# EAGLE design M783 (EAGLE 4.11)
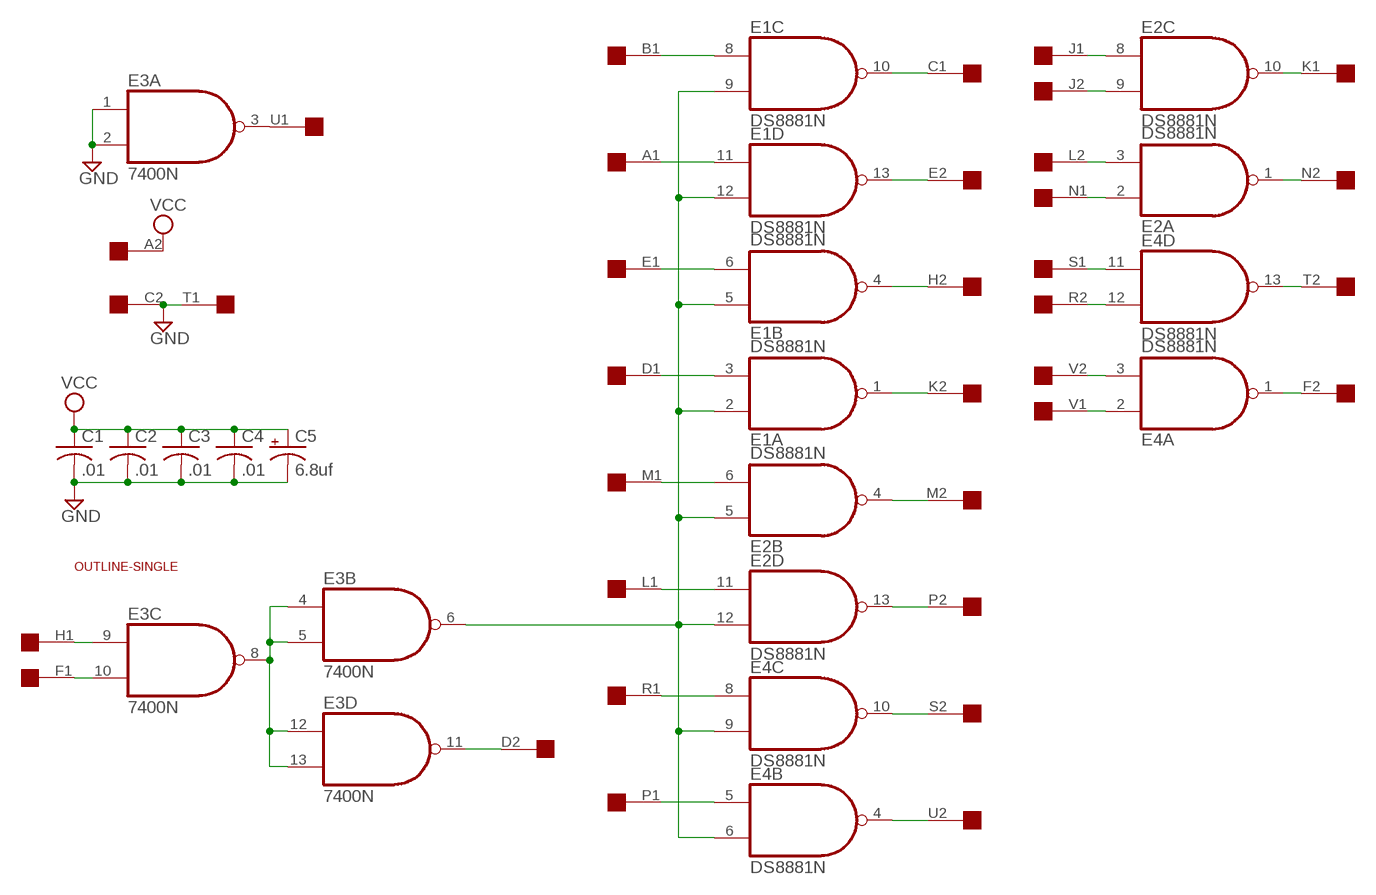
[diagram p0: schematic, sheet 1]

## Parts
C1  .01  C-US050-025X075  [C050-025X075]
C2  .01  C-US050-025X075  [C050-025X075]
C3  .01  C-US050-025X075  [C050-025X075]
C4  .01  C-US050-025X075  [C050-025X075]
C5  6.8uf  CPOL-USE15-5AXIAL  [E15-5]
E1  DS8881N  [DIL14]
E2  DS8881N  [DIL14]
E3  7400N  [DIL14]
E4  DS8881N  [DIL14]
U$1  SINGLE  [EDGE-CON2]
U$2  OUTLINE-SINGLE  [SINGLE]

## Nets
GND: C1.2 C2.2 C3.2 C4.2 C5.- E3.1(A:I0) E3.2(A:I1) U$1.C2 U$1.T1
N$1: E3.3(A:O) U$1.U1
N$2: E1.2(A:I0) E1.5(B:I0) E1.9(C:I1) E1.12(D:I1) E2.5(B:I0) E2.12(D:I1) E3.6(B:O) E4.6(B:I1) E4.9(C:I1)
N$3: E2.4(B:O) U$1.M2
N$4: E2.13(D:O) U$1.P2
N$5: E4.5(B:I0) U$1.P1
N$6: E4.8(C:I0) U$1.R1
N$7: E4.10(C:O) U$1.S2
N$8: E2.11(D:I0) U$1.L1
N$9: E4.4(B:O) U$1.U2
N$10: E2.6(B:I1) U$1.M1
N$11: E1.10(C:O) U$1.C1
N$12: E1.8(C:I0) U$1.B1
N$13: E1.13(D:O) U$1.E2
N$14: E1.11(D:I0) U$1.A1
N$15: E1.4(B:O) U$1.H2
N$16: E1.6(B:I1) U$1.E1
N$17: E1.1(A:O) U$1.K2
N$18: E1.3(A:I1) U$1.D1
N$19: E3.11(D:O) U$1.D2
N$20: E4.1(A:O) U$1.F2
N$21: E4.13(D:O) U$1.T2
N$22: E2.1(A:O) U$1.N2
N$23: E2.10(C:O) U$1.K1
N$24: E2.8(C:I0) U$1.J1
N$25: E2.9(C:I1) U$1.J2
N$26: E2.3(A:I1) U$1.L2
N$27: E2.2(A:I0) U$1.N1
N$28: E4.11(D:I0) U$1.S1
N$29: E4.12(D:I1) U$1.R2
N$30: E3.4(B:I0) E3.5(B:I1) E3.8(C:O) E3.12(D:I0) E3.13(D:I1)
N$31: E3.9(C:I0) U$1.H1
N$32: E3.10(C:I1) U$1.F1
N$33: E4.3(A:I1) U$1.V2
N$34: E4.2(A:I0) U$1.V1
VCC: C1.1 C2.1 C3.1 C4.1 C5.+ U$1.A2
Unconnected: U$1.B2

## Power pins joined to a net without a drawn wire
GND: E1.7(P:GND) E2.7(P:GND) E3.7(P:GND) E4.7(P:GND)
VCC: E1.14(P:VCC) E2.14(P:VCC) E3.14(P:VCC) E4.14(P:VCC)

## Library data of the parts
C1-C4 = rcl:C-US: CAPACITOR, American symbol
C5 = rcl:CPOL-US: POLARIZED CAPACITOR, American symbol
E1 E2 E4 = dec-con:DS8881: Quad 2-input NAND gate, open collector
E3 = 74xx-jameco:74*00: Quad 2-input NAND gate
U$1 = dec-con:SINGLE: Single-Height DEC board
U$2 = dec-con:OUTLINE-*: Board outlines for DEC boards.

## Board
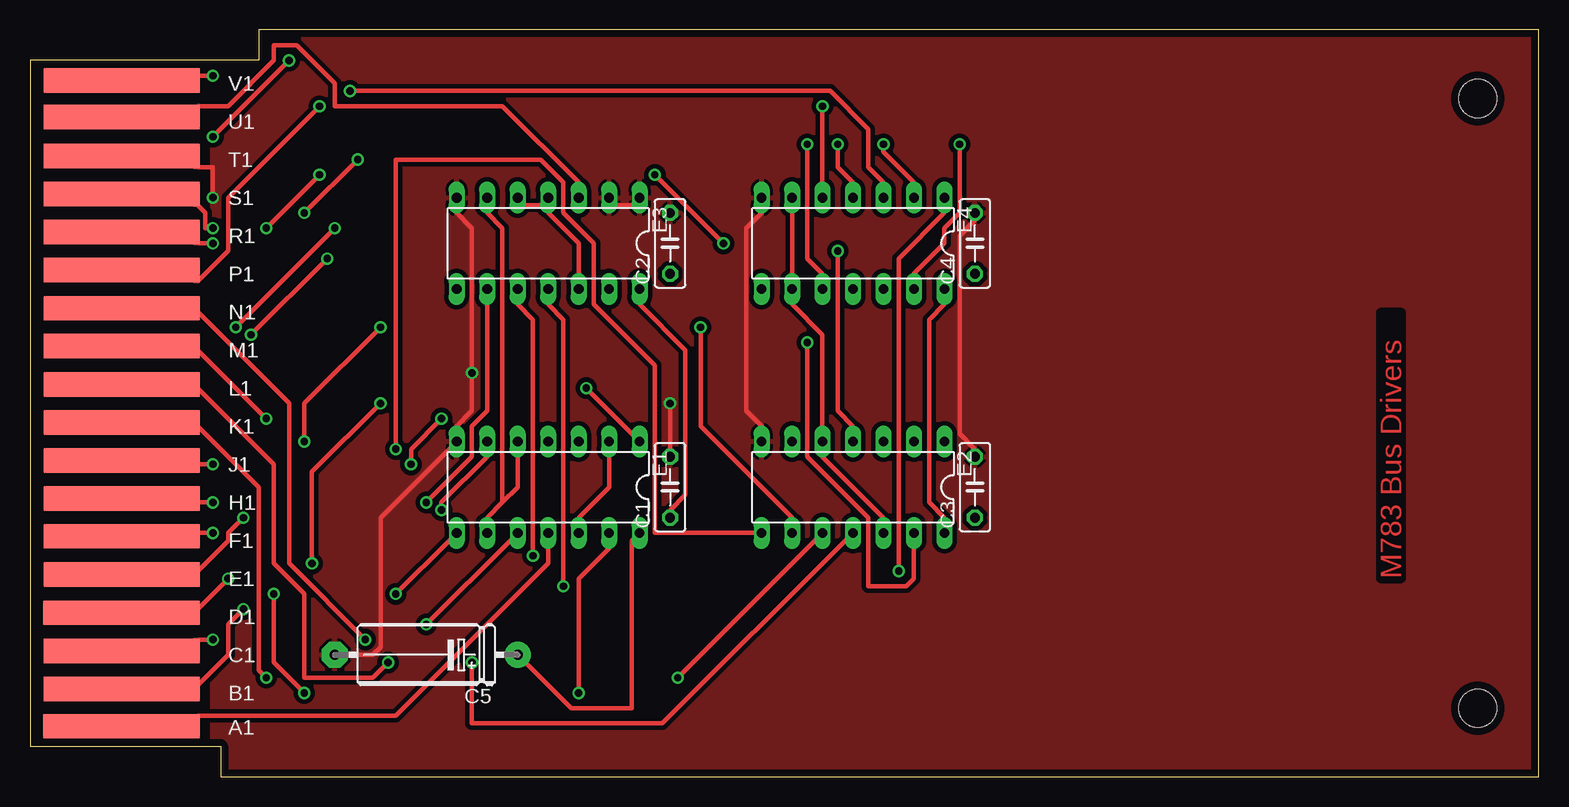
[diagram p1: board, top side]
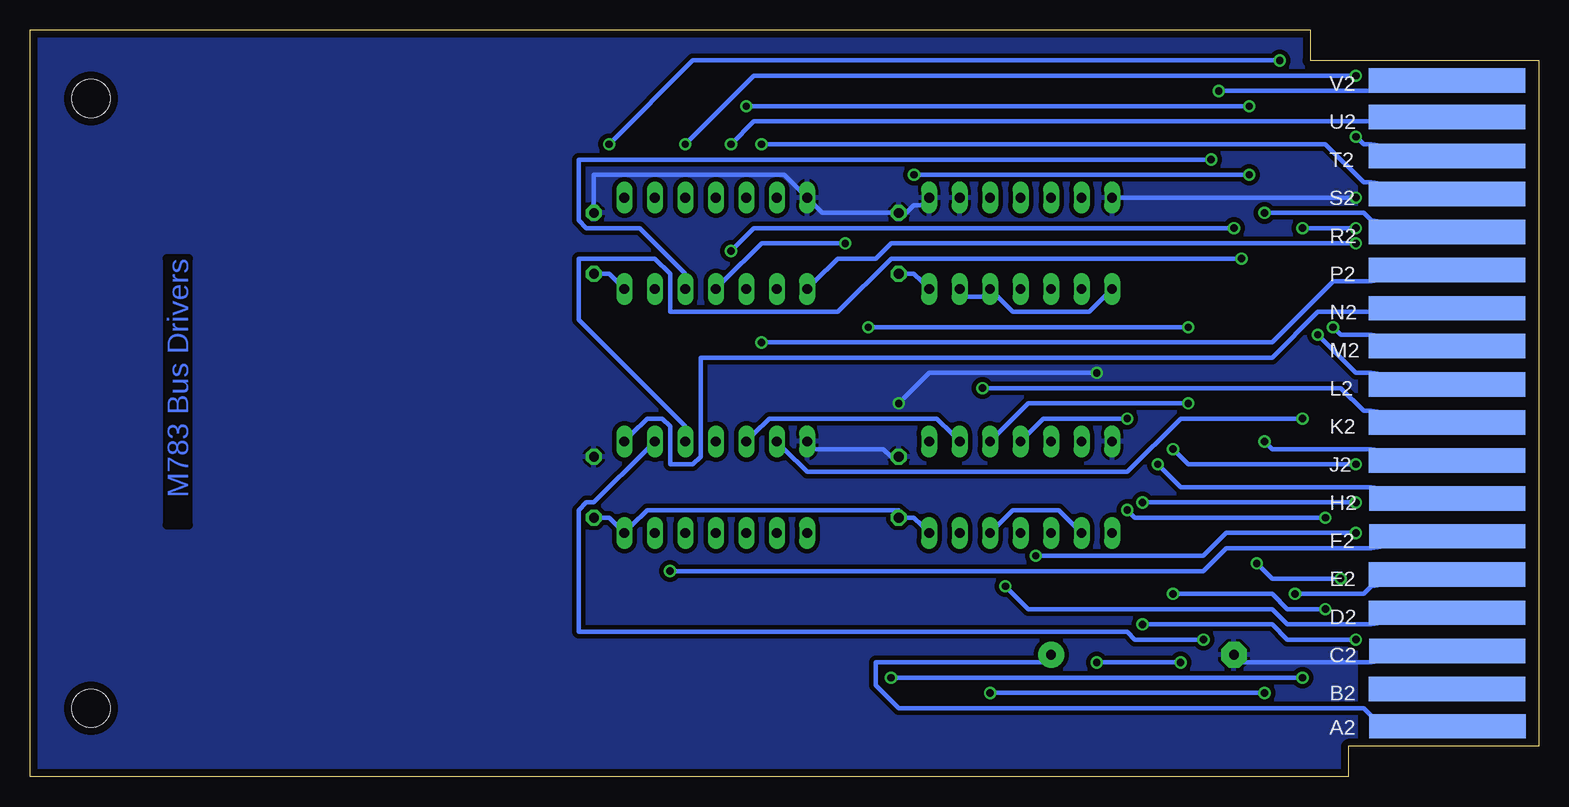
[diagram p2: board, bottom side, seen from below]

Size 125.73 x 62.23 mm. Coordinates in mm from the lower left corner, seen from the top.
Copper layers (1*16): Top 0.035mm / dielectric 1.5mm / Bottom 0.035mm
Design rules "15mils": minimum track width 15mil, minimum drill 24mil, track to track 15mil, track to pad 10mil, pad to pad 10mil, via to via 10mil, smd to smd 10mil, copper to edge 25mil, drill to drill 10mil, minimum pad ring 10mil, minimum via ring 8mil, stop-mask expansion 0mil, vias tented up to drill 0mil, thermal gap 10mil

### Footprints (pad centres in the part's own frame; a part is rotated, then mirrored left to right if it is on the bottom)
C050-025X075 = drill 0.813 octagon: 1 -2.54,0; 2 2.54,0
E15-5 = drill 0.813 pad 2.159 round: + -7.62,0 | drill 0.813 pad 2.159 octagon: - 7.62,0
DIL14 = drill 0.813 long: 1 -7.62,-3.81; 2 -5.08,-3.81; 3 -2.54,-3.81; 4 0,-3.81; 5 2.54,-3.81; 6 5.08,-3.81; 7 7.62,-3.81; 8 7.62,3.81; 9 5.08,3.81; 10 2.54,3.81; 11 0,3.81; 12 -2.54,3.81; 13 -5.08,3.81; 14 -7.62,3.81
EDGE-CON2 = smd 13.017 x 2.032: A1 7.633,4.207; B1 7.639,7.327; C1 7.636,10.489; D1 7.633,13.665; E1 7.642,16.84; F1 7.642,20.041; H1 7.642,23.19; J1 7.642,26.34; K1 7.642,29.515; L1 7.642,32.69; M1 7.642,35.89; N1 7.642,39.04; P1 7.642,42.24; R1 7.642,45.39; S1 7.642,48.565; T1 7.642,51.74; U1 7.642,54.966; V1 7.642,58.026 | smd 13.017 x 2.032 bottom: A2 7.614,4.207; B2 7.642,7.328; C2 7.617,10.49; D2 7.642,13.665; E2 7.642,16.84; F2 7.617,20.041; H2 7.617,23.19; J2 7.642,26.34; K2 7.642,29.515; L2 7.642,32.69; M2 7.642,35.89; N2 7.642,39.04; P2 7.642,42.24; R2 7.642,45.39; S2 7.642,48.565; T2 7.642,51.74; U2 7.642,54.966; V2 7.642,58.026
SINGLE = hole 3.175: 120.65,56.515; 120.65,5.715

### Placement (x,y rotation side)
C1  53.34,24.13 90 top
C2  53.34,44.45 90 top
C3  78.74,24.13 90 top
C4  78.74,44.45 90 top
C5  33.02,10.16 180 top
E1  43.18,24.13 180 top
E2  68.58,24.13 180 top
E3  43.18,44.45 180 top
E4  68.58,44.45 180 top
U$1  0,0 0 top
U$2  0,0 0 top

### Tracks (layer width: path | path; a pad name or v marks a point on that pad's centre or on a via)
GND  (via drill 0.61)
  Top 0.381: C3.2 78.74,27.3 77.47,28.57 77.47,45.09 78.74,46.35 C4.2 | E3.2 48.9,47.62 50.17,47.62 E3.1 | E2.7 60.96,29.21 59.69,30.48 59.69,45.72 60.96,46.99 E4.7 | E3.7 35.56,46.99 36.83,45.72 v36.83,33.66 36.83,30.48 35.56,29.21 E1.7 34.93,27.3 29.21,21.59 29.21,10.79 28.58,10.16 26.04,10.16 C5.- | v15.24,48.26 15.24,50.8 13.97,50.8 U$1.T1 | v53.34,31.11 53.34,27.3 C1.2
  Bottom 0.381: C1.2 53.98,26.67 54.61,27.3 60.33,27.3 E2.7 | E3.1 51.44,47.62 52.07,47.62 52.71,46.99 C2.2 53.98,46.99 59.69,46.99 60.33,47.62 E4.7 61.6,48.9 62.87,50.16 78.74,50.16 78.74,47.62 C4.2 | C5.- 24.77,9.53 13.97,9.53 U$1.C2 | v15.24,48.26 34.93,48.26 E3.7 | v53.34,31.11 50.8,33.66 v36.83,33.66
  pour Top (isolate 0.305): 15.24,62.23 125.73,62.23 125.73,0 15.24,0
  pour Bottom (isolate 0.305): 15.24,62.23 125.73,62.23 125.73,0 15.24,0
N$1
  Top 0.381: E3.3 45.72,49.53 39.37,55.88 25.4,55.88 25.4,57.78 22.23,60.96 20.32,60.96 20.32,59.69 16.51,55.88 13.97,55.88 U$1.U1
N$2
  Top 0.381: E4.6 63.5,46.99 63.5,41.91 E4.9 63.5,39.37 66.04,36.83 66.04,29.21 E2.5 66.04,26.67 71.12,21.59 E2.12 | E1.12 45.72,21.59 48.26,24.13 48.26,26.67 E1.2 | 39.37,22.86 40.64,24.13 40.64,26.67 E1.5 | 39.37,22.86 38.1,21.59 E1.9 | 39.37,22.86 39.37,45.72 38.1,46.99 E3.6
  Bottom 0.381: E1.12 45.09,20.95 43.82,22.23 40.01,22.23 38.74,20.95 E1.9 | E2.5 65.41,28.57 64.14,29.84 50.17,29.84 48.9,28.57 E1.2
N$3  (via drill 0.61)
  Top 0.381: v67.31,43.81 67.31,30.48 68.58,29.21 E2.4 | v17.15,37.47 v25.4,45.72
  Bottom 0.381: v67.31,43.81 65.41,45.72 v25.4,45.72 | v17.15,37.47 16.51,36.83 13.97,36.83 U$1.M2
N$4  (via drill 0.61)
  Top 0.381: v64.77,36.2 64.77,26.67 69.85,21.59 69.85,15.88 73.03,15.88 73.66,16.51 73.66,19.05 E2.13
  Bottom 0.381: v64.77,36.2 22.23,36.2 17.15,41.27 13.97,41.27 U$1.P2
N$5  (via drill 0.61)
  Top 0.381: v66.04,55.88 66.04,49.53 E4.5 | v24.13,55.88 16.51,48.26 16.51,43.81 13.97,41.27 U$1.P1
  Bottom 0.381: v24.13,55.88 v66.04,55.88
N$6  (via drill 0.61)
  Top 0.381: v15.24,44.45 13.97,44.45 U$1.R1
  Bottom 0.381: v15.24,44.45 53.98,44.45 55.25,43.18 58.42,43.18 60.33,41.27 E4.8
N$7  (via drill 0.61)
  Top 0.381: v64.77,52.7 64.77,43.18 66.04,41.91 E4.10
  Bottom 0.381: v64.77,52.7 17.78,52.7 14.61,49.53 13.97,49.53 U$1.S2
N$8  (via drill 0.61)
  Top 0.381: v36.83,9.53 36.83,4.45 52.71,4.45 67.95,19.68 E2.11 | v29.85,9.53 28.58,8.26 22.86,8.26 22.86,15.24 20.32,17.78 20.32,26.04 13.97,32.38 U$1.L1
  Bottom 0.381: v29.85,9.53 v36.83,9.53
N$9  (via drill 0.61)
  Top 0.381: v67.31,52.7 67.31,50.8 68.58,49.53 E4.4
  Bottom 0.381: v67.31,52.7 65.41,54.61 13.97,54.61 U$1.U2
N$10  (via drill 0.61)
  Top 0.381: v19.69,29.84 13.97,35.56 U$1.M1
  Bottom 0.381: v19.69,29.84 29.85,29.84 34.29,25.4 60.96,25.4 62.87,27.3 E2.6
N$11  (via drill 0.61)
  Top 0.381: v33.02,12.7 40.01,19.68 E1.10 | v15.24,11.43 13.97,11.43 U$1.C1
  Bottom 0.381: v33.02,12.7 22.23,12.7 20.96,11.43 v15.24,11.43
N$12  (via drill 0.61)
  Top 0.381: v30.48,15.24 34.93,19.68 E1.8 | v17.78,13.97 16.51,12.7 16.51,10.16 13.97,7.62 U$1.B1
  Bottom 0.381: v30.48,15.24 22.23,15.24 20.96,13.97 v17.78,13.97
N$13  (via drill 0.61)
  Top 0.381: v45.72,6.99 45.72,16.51 48.26,19.05 E1.13 | v22.86,6.99 20.32,9.53 v20.32,15.24
  Bottom 0.381: v22.86,6.99 v45.72,6.99 | v20.32,15.24 14.61,15.24 13.97,15.88 U$1.E2
N$14
  Top 0.381: E1.11 43.18,19.05 43.18,17.78 30.48,5.08 13.97,5.08 U$1.A1
N$15  (via drill 0.61)
  Top 0.381: v34.29,29.84 31.75,27.3 v31.75,26.04
  Bottom 0.381: v34.29,29.84 41.28,29.84 42.55,28.57 E1.4 | v31.75,26.04 29.85,24.13 13.97,24.13 U$1.H2
N$16  (via drill 0.61)
  Top 0.381: v34.29,22.23 34.29,22.86 38.1,26.67 E1.6 | v17.78,21.59 16.51,20.32 16.51,19.68 13.97,17.14 U$1.E1
  Bottom 0.381: v34.29,22.23 33.66,21.59 v17.78,21.59
N$17  (via drill 0.61)
  Top 0.381: v46.36,32.38 50.17,28.57 E1.1
  Bottom 0.381: v46.36,32.38 16.51,32.38 14.61,30.48 13.97,30.48 U$1.K2
N$18  (via drill 0.61)
  Top 0.381: v29.21,31.11 23.5,25.4 v23.5,17.78 | v16.51,16.51 13.97,13.97 U$1.D1
  Bottom 0.381: v29.21,31.11 42.55,31.11 45.09,28.57 E1.3 | v23.5,17.78 22.23,16.51 v16.51,16.51
N$19  (via drill 0.61)
  Top 0.381: v44.45,15.88 44.45,38.1 43.18,39.37 E3.11
  Bottom 0.381: v44.45,15.88 42.55,13.97 22.23,13.97 20.96,12.7 13.97,12.7 U$1.D2
N$20  (via drill 0.61)
  Top 0.381: v72.39,17.14 72.39,43.18 76.2,46.99 E4.1
  Bottom 0.381: v72.39,17.14 27.94,17.14 26.04,19.05 13.97,19.05 U$1.F2
N$21  (via drill 0.61)
  Top 0.381: v77.47,52.7 77.47,46.99 76.2,45.72 76.2,44.45 73.66,41.91 E4.13 | v15.24,53.34 v21.59,59.69
  Bottom 0.381: v77.47,52.7 70.49,59.69 v21.59,59.69 | v15.24,53.34 14.61,52.7 13.97,52.7 U$1.T2
N$22
  Bottom 0.381: E2.1 75.57,28.57 74.3,29.84 73.03,29.84 72.39,29.21 72.39,26.04 70.49,26.04 69.85,26.67 69.85,34.92 22.23,34.92 18.42,38.73 13.97,38.73 U$1.N2
N$23  (via drill 0.61)
  Top 0.381: v53.98,8.26 65.41,19.68 E2.10 | v19.69,8.26 19.05,8.89 19.05,24.13 13.97,29.21 U$1.K1
  Bottom 0.381: v19.69,8.26 v53.98,8.26
N$24  (via drill 0.61)
  Top 0.381: v30.48,27.3 30.48,51.44 42.55,51.44 44.45,49.53 44.45,46.99 46.99,44.45 46.99,39.37 52.07,34.29 52.07,20.32 60.33,20.32 E2.8 | v15.24,26.04 13.97,26.04 U$1.J1
  Bottom 0.381: v30.48,27.3 29.21,26.04 v15.24,26.04
N$25  (via drill 0.61)
  Top 0.381: v55.88,37.47 55.88,29.21 63.5,21.59 E2.9 | v29.21,37.47 22.86,31.11 v22.86,27.94
  Bottom 0.381: v29.21,37.47 v55.88,37.47 | v22.86,27.94 22.23,27.3 13.97,27.3 U$1.J2
N$26  (via drill 0.61)
  Top 0.381: v18.42,36.83 v24.77,43.18
  Bottom 0.381: v24.77,43.18 53.98,43.18 58.42,38.73 72.39,38.73 72.39,41.91 73.66,43.18 80.01,43.18 80.01,38.1 71.12,29.21 E2.3 | v18.42,36.83 15.24,33.66 13.97,33.66 U$1.L2
N$27  (via drill 0.61)
  Top 0.381: v27.94,11.43 21.59,17.78 21.59,31.11 13.97,38.73 U$1.N1
  Bottom 0.381: v27.94,11.43 33.66,11.43 34.29,12.06 80.01,12.06 80.01,22.23 79.38,22.86 78.74,22.86 74.3,27.3 E2.2
N$28  (via drill 0.61)
  Top 0.381: v52.07,50.16 v57.79,44.45 | v19.69,45.72 v24.13,50.16 | v15.24,45.72 14.61,45.72 14.61,46.99 13.97,47.62 U$1.S1
  Bottom 0.381: v57.79,44.45 64.77,44.45 67.95,41.27 E4.11 | v24.13,50.16 v52.07,50.16 | v15.24,45.72 v19.69,45.72
N$29  (via drill 0.61)
  Top 0.381: v22.86,46.99 v27.31,51.44
  Bottom 0.381: v27.31,51.44 80.01,51.44 80.01,46.35 79.38,45.72 74.93,45.72 71.12,41.91 E4.12 | v22.86,46.99 14.61,46.99 13.97,46.35 U$1.R2
N$30
  Top 0.381: E3.5 41.28,47.62 42.55,47.62 E3.4 43.18,46.99 45.72,44.45 45.72,41.91 E3.12
  Bottom 0.381: E3.8 36.2,40.01 37.47,38.73 43.82,38.73 45.09,40.01 E3.12 46.36,40.01 47.63,40.01 E3.13
N$31  (via drill 0.61)
  Top 0.381: v33.02,22.86 36.83,26.67 36.83,29.21 38.1,30.48 38.1,39.37 E3.9 | v15.24,22.86 13.97,22.86 U$1.H1
  Bottom 0.381: v15.24,22.86 v33.02,22.86
N$32  (via drill 0.61)
  Top 0.381: v41.91,18.41 41.91,38.1 40.64,39.37 E3.10 | v15.24,20.32 13.97,20.32 U$1.F1
  Bottom 0.381: v41.91,18.41 27.94,18.41 26.04,20.32 v15.24,20.32
N$33  (via drill 0.61)
  Top 0.381: v26.67,57.15 66.68,57.15 69.85,53.98 69.85,50.8 71.12,49.53 E4.3
  Bottom 0.381: v26.67,57.15 13.97,57.15 U$1.V2
N$34  (via drill 0.61)
  Top 0.381: v71.12,52.7 71.12,52.07 73.66,49.53 E4.2 | v15.24,58.42 13.97,58.42 U$1.V1
  Bottom 0.381: v71.12,52.7 65.41,58.42 v15.24,58.42
VCC
  Top 0.381: C1.1 53.34,22.23 54.61,23.5 54.61,35.56 50.8,39.37 E3.14 | E4.14 76.2,39.37 74.93,38.1 74.93,22.86 76.2,21.59 E2.14 | C5.+ 41.28,9.53 45.09,5.71 50.17,5.71 50.17,19.68 E1.14
  Bottom 0.381: E4.14 76.84,41.27 77.47,41.91 78.11,41.91 C4.1 | C3.1 78.11,21.59 77.47,21.59 76.84,20.95 E2.14 75.57,20.95 74.3,22.23 53.34,22.23 C1.1 52.71,21.59 52.07,21.59 51.44,20.95 E1.14 | E3.14 51.44,41.27 52.07,41.91 52.71,41.91 C2.1 | U$1.A2 13.97,5.08 14.61,5.71 53.34,5.71 55.25,7.62 55.25,9.53 41.28,9.53 C5.+

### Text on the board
Top: M783 Bus Drivers
Bottom: M783 Bus Drivers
